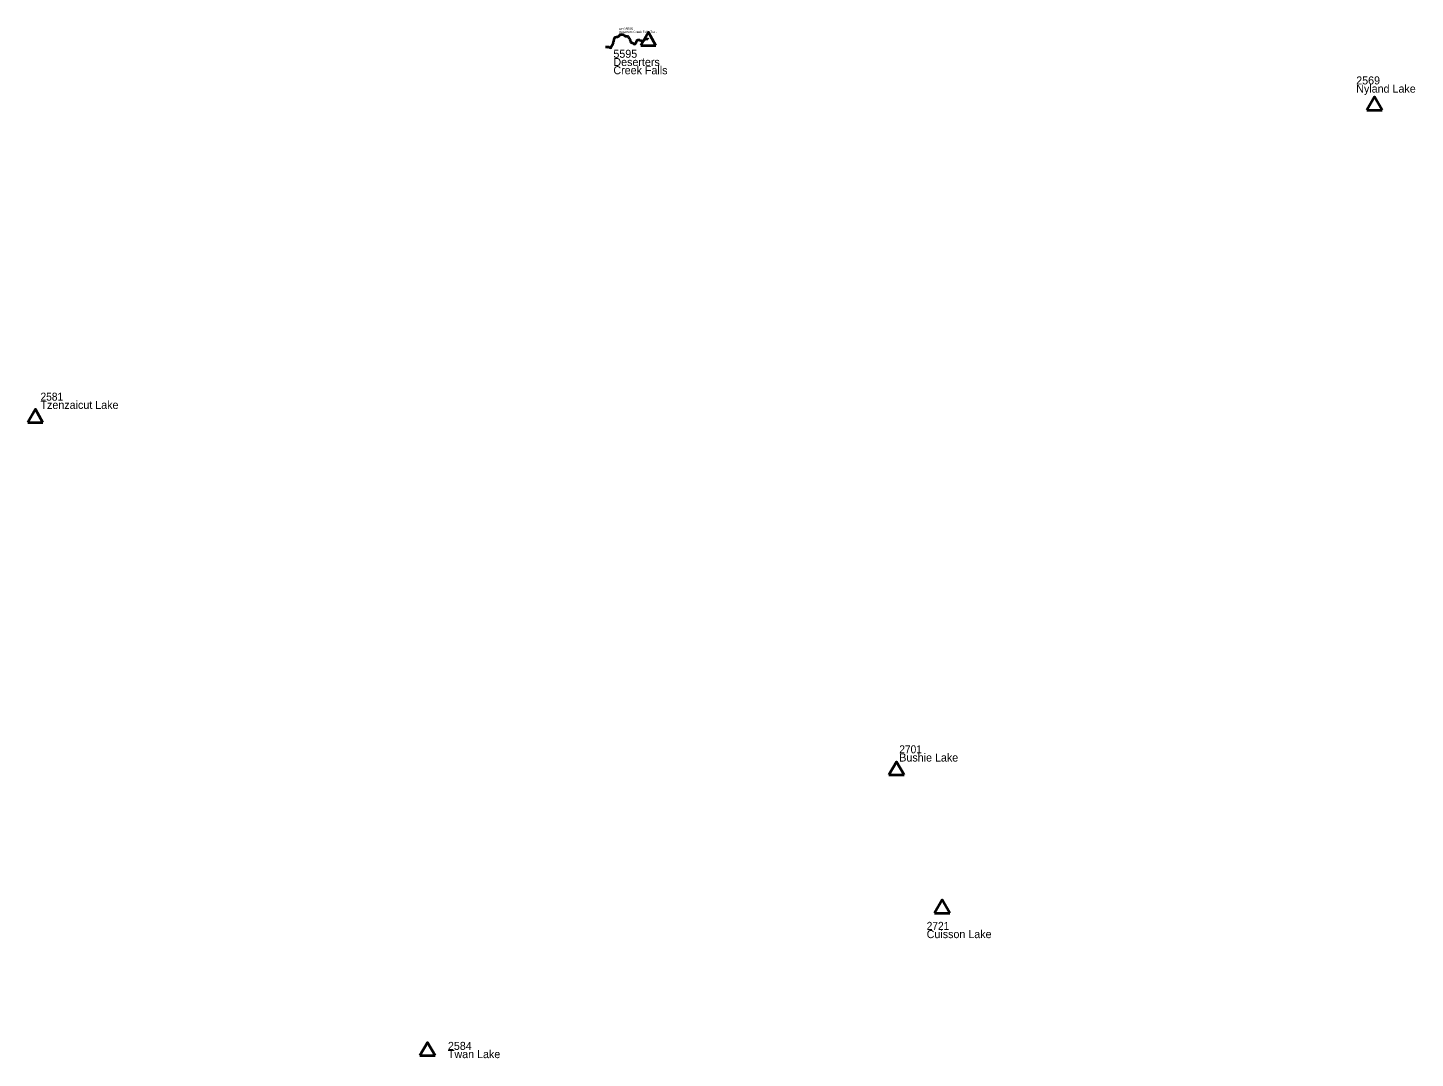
# Model space of a CAD drawing. Extents: x 322505 to 642419, y 5806860 to 5919753.
# Drawn here: x 507453 to 568120, y 5806860 to 5851913 of the extents above; entities that cross this region are included whole.
import ezdxf
from ezdxf.enums import TextEntityAlignment as Align

# ---------------------------------------------------------------- set-up
doc = ezdxf.new("R2010")
doc.units = 0
doc.header["$LTSCALE"] = 140
doc.layers.add('1', color=7, linetype='Continuous', lineweight=40)
doc.layers.add('4', color=7, linetype='Continuous', lineweight=40)

msp = doc.modelspace()

# ---------------------------------------------------------------- linework, layer by layer
at = {"layer": '1'}
for p, q in [((534257.1, 5851139.9), (534922.4, 5851139.9)), ((566009.3, 5848314.9), (566674.6, 5848314.9)), ((507453.4, 5834659.9), (508118.8, 5834659.9)), ((545104.3, 5819247.9), (545769.6, 5819247.9)), ((547102.1, 5813209.9), (547767.4, 5813209.9)), ((524603.1, 5806975.9), (525268.4, 5806975.9))]:
    msp.add_line(p, q, dxfattribs=at)
for points in [[(534922.4, 5851139.9), (534589.8, 5851716.1), (534257.1, 5851139.9)], [(566674.6, 5848314.9), (566341.9, 5848891.1), (566009.3, 5848314.9)], [(508118.8, 5834659.9), (507786.1, 5835236.1), (507453.4, 5834659.9)], [(545769.6, 5819247.9), (545436.9, 5819824.1), (545104.3, 5819247.9)], [(547767.4, 5813209.9), (547434.8, 5813786.1), (547102.1, 5813209.9)], [(525268.4, 5806975.9), (524935.8, 5807552.1), (524603.1, 5806975.9)]]:
    msp.add_lwpolyline(points, dxfattribs=at)
at = {"layer": '4'}
for points in [[(532998.6, 5851133.5), (533014.8, 5851147), (533021.8, 5851160.8), (533028.8, 5851174), (533039.2, 5851200), (533042.7, 5851210.2), (533049.7, 5851230.1), (533052.6, 5851242.3), (533059.1, 5851265.2), (533061.5, 5851276.5), (533067.4, 5851299.4), (533074.4, 5851321.8), (533080.8, 5851343.2), (533083.3, 5851351.3), (533089.2, 5851375.8), (533095.6, 5851400.2), (533100.5, 5851422.1), (533104.5, 5851436.4), (533110.4, 5851459.8), (533124.9, 5851484.3), (533139.6, 5851496.1), (533159.8, 5851503.4), (533177.5, 5851511.1), (533197.3, 5851520.4), (533212.1, 5851517.4), (533223.7, 5851516.5), (533244, 5851519.7), (533267.9, 5851524.9), (533287.1, 5851530.6), (533297.2, 5851539.3), (533313.8, 5851560.8), (533320.3, 5851573.6), (533327.8, 5851592.4), (533349.5, 5851607.8), (533366.8, 5851614), (533390.1, 5851619.8), (533407.9, 5851619.9), (533425.1, 5851620.5), (533447, 5851617.1), (533467.3, 5851613.7), (533488.7, 5851608.8), (533509.1, 5851602.8), (533533.6, 5851588.2)], [(533533.6, 5851588.2), (533548.4, 5851570.5), (533558.2, 5851561.4), (533582.6, 5851551.4), (533592.8, 5851551), (533630.9, 5851547.2), (533633.4, 5851547.1)], [(533633.4, 5851547.1), (533649.7, 5851546.3), (533664.5, 5851546.4), (533680.8, 5851539.4), (533706.3, 5851523.8), (533718.1, 5851507.1), (533720.1, 5851503.6)], [(533720.1, 5851503.6), (533726.3, 5851492.9), (533735.7, 5851471.1), (533746.5, 5851450.3), (533758.9, 5851428), (533767.6, 5851412.3), (533776.4, 5851396.1), (533788.2, 5851378.9), (533792.9, 5851365.2), (533798.7, 5851338.3), (533800.8, 5851321.5), (533805.1, 5851297.2), (533807.8, 5851273.3), (533808.2, 5851266.1)], [(533922.9, 5851231.9), (533959.3, 5851205.9), (533995.2, 5851193.1), (534024.2, 5851225.8), (534037.1, 5851245.5), (534050, 5851268.3), (534062.8, 5851297.7), (534072.5, 5851314.1), (534078.8, 5851333.6), (534088.5, 5851353.2), (534101.4, 5851366.4), (534111.1, 5851372.9), (534130.6, 5851382.8), (534159.8, 5851389.5), (534172.9, 5851386.4), (534192.4, 5851383.3), (534208.7, 5851376.9), (534225.1, 5851370.5), (534238.1, 5851364.1), (534264.2, 5851354.5), (534283.9, 5851341.6), (534296.9, 5851335.2), (534306.7, 5851332), (534329.5, 5851332.1), (534345.8, 5851332.2), (534362, 5851342.1), (534387.9, 5851355.3), (534400.9, 5851365.2), (534410.6, 5851375), (534423.5, 5851384.9), (534433.2, 5851394.7), (534443, 5851401.3), (534449.4, 5851404.6), (534468.9, 5851421), (534485.1, 5851424.4), (534504.6, 5851431), (534533.9, 5851434.5), (534546.9, 5851431.3), (534560, 5851428.1), (534566.5, 5851421.7), (534573.8, 5851419.3)], [(532716.6, 5851075.9), (532733.3, 5851078.5), (532755.6, 5851084.8), (532765.8, 5851084.8), (532781.1, 5851078.3), (532796.9, 5851064.7), (532835, 5851072.1), (532859.3, 5851075.8), (532879.2, 5851067.8), (532903.7, 5851054.7), (532918, 5851047.7), (532941.9, 5851041.3), (532961.1, 5851052.6), (532966.1, 5851066.9), (532970.1, 5851080.6), (532974.4, 5851105), (532987.7, 5851122.5), (532998.6, 5851133.5)], [(533808.2, 5851266.1), (533819.6, 5851264.7), (533835.8, 5851265.3), (533853.6, 5851265.5), (533875.5, 5851259.5), (533890.3, 5851253), (533904.6, 5851241.4), (533922.9, 5851231.9)]]:
    msp.add_lwpolyline(points, dxfattribs=at)

# ---------------------------------------------------------------- texts
at = {"layer": '1'}
for s, p in [('5595', (533059.8, 5850600.1)), ('Creek Falls', (533059.8, 5849880.1)), ('Deserters', (533059.8, 5850240.1)), ('2569', (565538.7, 5849435.3)), ('Nyland Lake', (565538.7, 5849075.3)), ('Tzenzaicut Lake', (508011.2, 5835248.7)), ('Bushie Lake', (545560, 5819831.7)), ('Cuisson Lake', (546758.3, 5812111.2)), ('Twan Lake', (525824.3, 5806864.8)), ('2584', (525824.3, 5807224.8))]:
    msp.add_text(s, height=350, dxfattribs=at).set_placement(p)
at = {"layer": '1', "width": 0.95}
for s, p in [('2581', (508011.2, 5835608.7)), ('2701', (545560, 5820191.7)), ('2721', (546758.3, 5812471.2))]:
    msp.add_text(s, height=350, dxfattribs=at).set_placement(p)
at = {"layer": '4'}
for s, p in [('REC5595', (533610.3, 5851809.8)), ('Deserters Creek Falls Trail', (534118.4, 5851680.6))]:
    msp.add_text(s, height=100, rotation=0.398, dxfattribs=at).set_placement(p, align=Align.CENTER)

doc.saveas('drawing.dxf')
